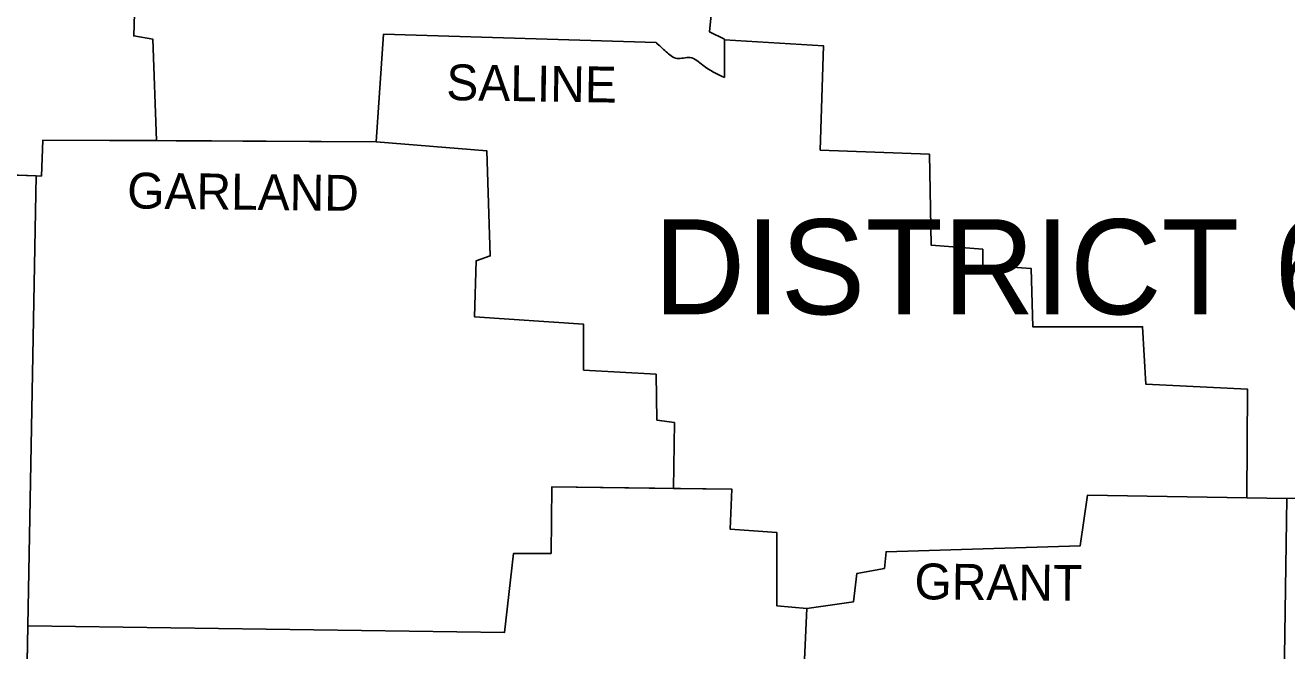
# Model space of a CAD drawing. Extents: x -28335 to 1228743, y -22428 to 152440.
# Drawn here: x 27348 to 30779, y 10174 to 11875 of the extents above; entities that cross this region are included whole.
import ezdxf

# ---------------------------------------------------------------- set-up
doc = ezdxf.new("R2010")
doc.units = 0
doc.layers.add('Level 16', color=7, linetype='Continuous')
doc.layers.add('Level 8', color=7, linetype='Continuous')

msp = doc.modelspace()

# ---------------------------------------------------------------- linework, layer by layer
at = {"layer": 'Level 16'}
for p, q in [((29249.5, 11835.5), (29249.5, 11732.6)), ((29249.5, 11835.5), (29519.1, 11818.6)), ((29519.1, 11818.6), (29510, 11535.5)), ((27396.5, 11562.7), (27392.8, 11464.7)), ((26490.4, 11499.2), (27378.4, 11465.3)), ((27378.4, 11465.3), (26490.4, 11499.2)), ((27378.4, 11465.3), (27355.7, 10242)), ((27378.4, 11465.3), (27392.8, 11464.7)), ((27392.8, 11464.7), (27378.4, 11465.3)), ((29811.3, 11277.2), (29951.8, 11265.9)), ((29951.8, 11265.9), (29951.8, 11222.9)), ((29951.8, 11222.9), (30083.2, 11213.8)), ((30083.2, 11213.8), (30087.7, 11055.2)), ((29066, 10801.5), (29113.6, 10794.7)), ((29113.6, 10794.7), (29111.2, 10615.7)), ((30669.9, 10590.4), (30778.6, 10588.6)), ((30778.6, 10588.6), (31279.1, 10590.6)), ((27355.7, 10242), (27352, 10042.7))]:
    msp.add_line(p, q, dxfattribs=at)
for points in [[(29249.5, 11732.6), (29249.5, 11836.8), (29208.8, 11857.1), (29224.6, 12015.7), (29503.2, 12031.6), (29512.3, 12119.9), (29809.1, 12131.2), (29802.3, 12192.4), (29807.4, 12191.8)], [(29965.4, 12174.3), (29807.4, 12191.8), (29802.3, 12192.4), (29809.1, 12131.2), (29512.3, 12119.9), (29503.2, 12031.6), (29224.6, 12015.7), (29208.8, 11857.1), (29249.5, 11836.8), (29249.5, 11835.5)], [(27786.1, 12022.5), (27738.6, 12008.9), (27727.2, 11947.8), (27691, 11950), (27679.7, 11918.3), (27645.7, 11907), (27643.4, 11845.8)], [(27705, 11561.1), (27695.5, 11836.8), (27643.4, 11845.8), (27645.7, 11907)], [(27643.4, 11845.8), (27695.5, 11836.8), (27705, 11561.1)], [(27705, 11561.1), (28302.6, 11558.1), (28323, 11850.4), (29063.8, 11827.7)], [(29063.8, 11827.7), (28323, 11850.4), (28302.6, 11558.1)], [(30669.9, 10590.4), (30672.1, 10885.4), (30395.8, 10898.9), (30386.7, 11055.2), (30087.7, 11055.2), (30083.2, 11213.8), (29951.8, 11222.9), (29951.8, 11265.9), (29811.3, 11277.2), (29806.8, 11524.2), (29510, 11535.5), (29519.1, 11818.6), (29249.5, 11835.5)], [(27392.8, 11464.7), (27396.5, 11562.7), (27705, 11561.1)], [(28302.6, 11558.1), (27705, 11561.1), (27396.5, 11562.7)], [(29111.2, 10615.7), (29113.6, 10794.7), (29066, 10801.5), (29063.8, 10926.1), (28866.7, 10937.5), (28866.7, 11062), (28569.9, 11082.4), (28574.5, 11234.2), (28613, 11247.8), (28603.9, 11533.2), (28302.6, 11558.1)], [(28302.6, 11558.1), (28603.9, 11533.2), (28613, 11247.8)], [(29510, 11535.5), (29806.8, 11524.2), (29811.3, 11277.2)], [(27352, 10042.7), (27355.7, 10242), (27378.4, 11465.3)], [(28613, 11247.8), (28574.5, 11234.2), (28569.9, 11082.4), (28866.7, 11062)], [(28866.7, 11062), (28866.7, 10937.5), (29063.8, 10926.1), (29066, 10801.5)], [(30087.7, 11055.2), (30386.7, 11055.2), (30395.8, 10898.9)], [(30395.8, 10898.9), (30672.1, 10885.4), (30669.9, 10590.4)], [(29473.8, 10289.6), (29392.2, 10296.4), (29392.2, 10495.7), (29265.4, 10504.8), (29269.9, 10613.5), (28780.6, 10620.3), (28778.3, 10439.1), (28676.4, 10439.1), (28651.5, 10223.9), (27355.7, 10242)], [(27355.7, 10242), (28651.5, 10223.9), (28676.4, 10439.1), (28778.3, 10439.1), (28780.6, 10620.3), (29111.2, 10615.7)], [(29111.2, 10615.7), (29269.9, 10613.5), (29265.4, 10504.8), (29392.2, 10495.7), (29392.2, 10296.4), (29473.8, 10289.6)], [(30778.6, 10588.6), (30669.9, 10590.4), (30237.2, 10597.7), (30216.8, 10459.5), (29689, 10443.6), (29684.5, 10398.3), (29609.7, 10384.7), (29600.6, 10307.7), (29473.8, 10289.6)], [(29473.8, 10289.6), (29600.6, 10307.7), (29609.7, 10384.7), (29684.5, 10398.3), (29689, 10443.6), (30216.8, 10459.5), (30237.2, 10597.7), (30669.9, 10590.4)], [(30706.1, 9098.1), (30712.9, 9666.7), (30765, 9668.9), (30778.6, 10588.6)], [(29473.8, 10289.6), (29472.8, 10268.9), (29446.6, 9696.1), (29426.2, 9702.9), (29428.5, 9397.4)], [(29426.2, 9702.9), (29446.6, 9696.1), (29472.8, 10268.9), (29473.8, 10289.6)], [(27355.7, 10242), (27355.7, 10242)]]:
    msp.add_lwpolyline(points, dxfattribs=at)
for points in [[(29063.8, 11827.7), (29091, 11802.8), (29120.4, 11784.7), (29156.6, 11786.9), (29190.6, 11766.5), (29249.5, 11732.6)], [(29249.5, 11732.6), (29190.6, 11766.5), (29156.6, 11786.9), (29120.4, 11784.7), (29091, 11802.8), (29063.8, 11827.7)]]:
    msp.add_spline(points, degree=3, dxfattribs=at)
at = {"layer": 'Level 8'}
msp.add_line((27378.4, 11465.3), (27352, 10042.7), dxfattribs=at)
for points in [[(29965.4, 12174.3), (29802.3, 12192.4), (29809.1, 12131.2), (29512.3, 12119.9), (29503.2, 12031.6), (29224.6, 12015.7), (29208.8, 11857.1), (29249.5, 11836.8), (29249.5, 11732.6)], [(27645.7, 11907), (27643.4, 11845.8), (27695.5, 11836.8), (27705, 11561.1)], [(29063.8, 11827.7), (28323, 11850.4), (28302.6, 11558.1), (27396.5, 11562.7), (27392.8, 11464.7)], [(29249.5, 11835.5), (29519.1, 11818.6), (29510, 11535.5), (29806.8, 11524.2), (29811.3, 11277.2), (29951.8, 11265.9), (29951.8, 11222.9), (30083.2, 11213.8), (30087.7, 11055.2), (30386.7, 11055.2), (30395.8, 10898.9), (30672.1, 10885.4), (30669.9, 10590.4)], [(28302.6, 11558.1), (28603.9, 11533.2), (28613, 11247.8), (28574.5, 11234.2), (28569.9, 11082.4), (28866.7, 11062), (28866.7, 10937.5), (29063.8, 10926.1), (29066, 10801.5), (29113.6, 10794.7), (29111.2, 10615.7)], [(27378.4, 11465.3), (26490.4, 11499.2)], [(27392.8, 11464.7), (27378.4, 11465.3)], [(27355.7, 10242), (28651.5, 10223.9), (28676.4, 10439.1), (28778.3, 10439.1), (28780.6, 10620.3), (29269.9, 10613.5), (29265.4, 10504.8), (29392.2, 10495.7), (29392.2, 10296.4), (29473.8, 10289.6), (29472.8, 10268.9)], [(29473.8, 10289.6), (29600.6, 10307.7), (29609.7, 10384.7), (29684.5, 10398.3), (29689, 10443.6), (30216.8, 10459.5), (30237.2, 10597.7), (30778.6, 10588.6)], [(30778.6, 10588.6), (30765, 9668.9), (30712.9, 9666.7), (30706.1, 9098.1)], [(30778.6, 10588.6), (30765, 9668.9), (30712.9, 9666.7)], [(32215.6, 10594.2), (31279.1, 10590.6), (30778.6, 10588.6)], [(29473.8, 10289.6), (29446.6, 9696.1), (29426.2, 9702.9), (29428.5, 9397.4)]]:
    msp.add_lwpolyline(points, dxfattribs=at)
msp.add_spline([(29249.5, 11732.6), (29190.6, 11766.5), (29156.6, 11786.9), (29120.4, 11784.7), (29091, 11802.8), (29063.8, 11827.7)], degree=3, dxfattribs=at)

# ---------------------------------------------------------------- texts
for s, rotation, p in [('SALINE', 359.1492, (28492.9, 11671.4)), ('GARLAND', 359.3658, (27625.3, 11376.9)), ('GRANT', 359.4032, (29766, 10314.5))]:
    msp.add_text(s, height=97.42, rotation=rotation, dxfattribs=at).set_placement(p)
msp.add_text('DISTRICT 6', height=258.24, dxfattribs=at).set_placement((29057, 11089.2))

doc.saveas('drawing.dxf')
